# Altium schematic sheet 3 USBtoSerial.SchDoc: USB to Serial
size A4
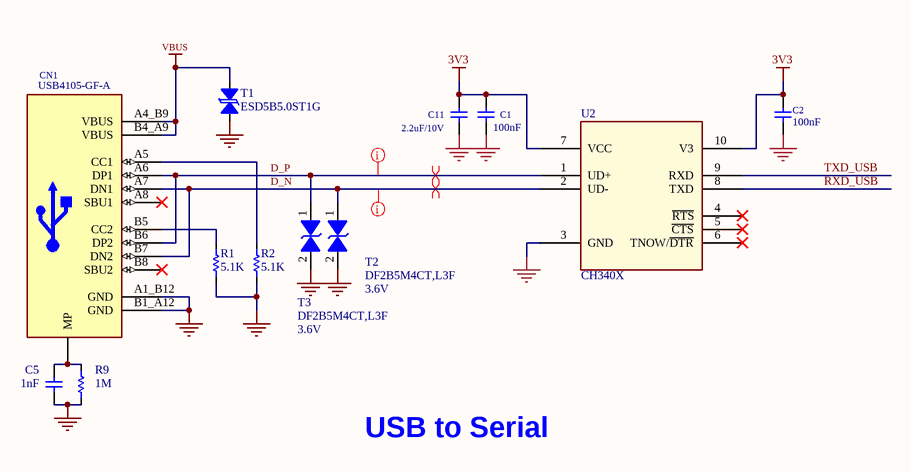
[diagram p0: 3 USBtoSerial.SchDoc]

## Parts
C1  100nF  [CAP 0402/1005]
C2  100nF  [CAP 0402/1005]
C5  1nF  [CAP 0402/1005]
C11  2.2uF/10V  [CAP 0402/1005]
CN1  USB4105-GF-A  [USB/ GCT_USB4105-GF-A]
R1  5.1K  [RES 0402/1005]
R2  5.1K  [RES 0402/1005]
R9  1M  [RES 0402/1005]
T1  ESD5B5.0ST1G  [SOD523]
T2  DF2B5M4CT,L3F  Working Voltage: 3.6V  [DFN1006-2L]
T3  DF2B5M4CT,L3F  Working Voltage: 3.6V  [DFN1006-2L]
U2  CH340X  [MSOP-10]

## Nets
3V3: C1.2 C2.2 C11.2 U2.7(VCC) U2.10(V3)
GND: C1.1 C2.1 C5.1 C11.1 CN1.A1_B12(GND) CN1.B1_A12(GND) R1.1 R2.1 R9.1 T1.1 T2.2(K) T3.2(K) U2.3(GND)
VBUS: CN1.A4_B9(VBUS) CN1.B4_A9(VBUS) T1.2
D_N: CN1.A7(DN1) CN1.B7(DN2) T2.1(A) U2.2(UD-)
D_P: CN1.A6(DP1) CN1.B6(DP2) T3.1(A) U2.1(UD+)
RXD_USB: U2.8(TXD)
TXD_USB: U2.9(RXD)
NetC5_2: C5.2 CN1.MP R9.2
NetCN1_A5: CN1.A5(CC1) R2.2
NetCN1_B5: CN1.B5(CC2) R1.2

Not connected (* = marked no-connect by the designer): CN1 A8(SBU1)* B8(SBU2)*; U2 4(~{RTS})* 5(~{CTS})* 6(TNOW/~{DTR})*

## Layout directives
net class 90d: D_N, D_P
differential pair: D_N, D_P

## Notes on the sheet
- USB to Serial

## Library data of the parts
C1 C2 = Cap: MLCC
C5 C11 = Cap: Capacitor MLCC
CN1 = CON/ USB4105-GF-A: USB-C Connector; MF: GCT
R1 R2 R9 = Res1_1: Resistor
T1 = TVS Diode: ESD Diode, Bi-direction, SOD-523
T2 T3 = Diode TVS: TVS Diode, Bidirectional, 3.6V, 0.3pF(max), SOD-882-2
U2 = CH340X: USB to Serial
